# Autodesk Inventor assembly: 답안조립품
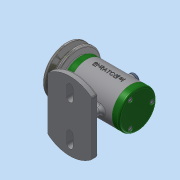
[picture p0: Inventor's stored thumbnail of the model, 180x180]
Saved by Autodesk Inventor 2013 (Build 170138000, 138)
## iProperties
Created: 2017-12
Part Number: 답안조립품
Document SubType Name: Assembly
Designer: dgall
Author: dgall
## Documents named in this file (14)
- C:\Users\dgall\Desktop\471207V1023\답안조립품.iam
- C:\Users\dgall\Desktop\471207V1023\본체.ipt
- C:\Users\dgall\Desktop\471207V1023\베어링 15 x 32 x 9.ipt
- C:\Users\dgall\Desktop\471207V1023\축.ipt
- C:\Users\dgall\Desktop\471207V1023\뒤커버.ipt
- C:\Users\dgall\Desktop\471207V1023\앞커버.ipt
- C:\Users\dgall\Desktop\471207V1023\오일 실 15 25 7.ipt
- C:\Users\dgall\Desktop\471207V1023\V벨트풀리.ipt
- C:\Users\dgall\Desktop\471207V1023\키 3 x 3 x 12.ipt
- C:\Users\dgall\Desktop\471207V1023\너트 M 8.ipt
- C:\Users\dgall\Desktop\471207V1023\스프링와셔 8.ipt
- C:\Users\dgall\Desktop\471207V1023\와셔 8x17.ipt
- C:\Users\dgall\Desktop\471207V1023\고무캡.ipt
- C:\Users\dgall\Desktop\471207V1023\볼트 M4 x 12.ipt
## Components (2 placed, 2 different names)
1. V벨트풀리:1
2. 고무캡:1
